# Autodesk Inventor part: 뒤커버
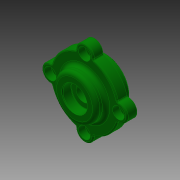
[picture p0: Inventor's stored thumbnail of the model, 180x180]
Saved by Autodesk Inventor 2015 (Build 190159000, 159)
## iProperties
Created: 2016-05
Part Number: 뒤커버
Document SubType Name: Modeling
Designer: mduedu
Density: 2.71 g/cm^3
Material: 알루미늄 6061
Appearance: 진녹색
Author: mduedu
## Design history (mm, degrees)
sketch "스케치1"
  geometry: C1 r 20 at (0, 0); C2 r 27.5 at (0, 0); 1 further point
  constraints: 2 centre point, 2 coincident
  dimensions: "d33" = 55 diameter of C2; "d34" = 40 diameter of C1
extrude "돌출1" new body sketch "스케치1" distance "d0" = 8; taper "d1" = 0 deg
extrude "돌출2" join sketch "스케치1" distance "d2" = 8; taper "d3" = 0 deg; dims "d35" = 9, "d36" = 0
sketch "스케치6"
  geometry: C1 r 17.5 at (0, 0); 2 further points
  constraints: 2 coincident, 1 centre point
  dimensions: "d42" = 35 diameter of C1
extrude "돌출4" join sketch "스케치6" distance "d43" = 8; taper "d44" = 0 deg
sketch "스케치4"
  geometry: L1 (0, -9)-(0, 16); L2 (-15, -9)-(-15, 0); L3 (-15, 0)-(-10, 0); L4 (-10, 0)-(-10, 3); L5 (-10, 3)-(-6, 3); L6 (-6, 3)-(-6, 8.7); L7 (-6, 8.7)-(-10, 8.7); L8 (-10, 8.7)-(-10, 16); L9 (20, -9)-(-20, -9) reference; L10 (17.5, 16)-(-17.5, 16) reference; 1 further point
  constraints: 16 end point, 6 parallel, 3 point on line, 2 midpoint, 2 perpendicular, 1 vertical
  dimensions: "d15" = 30 diameter of L2 L1; "d16" = 20 diameter of L8 L1; "d18" = 9 distance of L2.start L2.end; "d19" = 3 distance of L3.end L4.end; "d20" = 20 diameter of L4 L1; "d21" = 12 diameter of L6 L1; "d45" = 7.3 distance of L7.end L8.end
revolve "회전1" sketch "스케치4" stored, may be unused: angle "d22" = 90 deg
fillet "모깎기2" dims "d23" = 3
fillet "모깎기3" dims "d24" = 0.3
chamfer "모따기2" distance "d46" = 1; stored, may be unused: second distance "d47" = 2, angle "d48" = 45 deg
sketch "스케치7"
  geometry: C1 r 7 at (0, 27.5); 2 further points
  constraints: 3 vertical alignment, 1 centre point, 2 other
  dimensions: "d54" = 14 diameter of C1
extrude "돌출5" join sketch "스케치7" stored distance "d55" = 10; taper "d56" = 0 deg
fillet "모깎기6" dims "d57" = 1
sketch "스케치10"
  geometry: C1 r 17.5 at (0, 0) reference; A1 r 27.5 centre (0, 0) between (26.395, 7.718) and (7.718, 26.395) reference; A2 r 1 centre (7.999, 27.355) between (6.999, 27.373) and (7.718, 26.395) reference; A3 r 7 centre (0, 27.5) between (6.999, 27.373) and (-6.999, 27.373) reference; A4 r 1 centre (-7.999, 27.355) between (-7.718, 26.395) and (-6.999, 27.373) reference; A5 r 27.5 centre (0, 0) between (-7.718, 26.395) and (-26.395, 7.718) reference; A6 r 1 centre (-27.355, 7.999) between (-27.373, 6.999) and (-26.395, 7.718) reference; A7 r 7 centre (-27.5, 0) between (-27.373, 6.999) and (-27.373, -6.999) reference; A8 r 1 centre (-27.355, -7.999) between (-26.395, -7.718) and (-27.373, -6.999) reference; A9 r 27.5 centre (0, 0) between (-26.395, -7.718) and (-7.718, -26.395) reference; A10 r 1 centre (-7.999, -27.355) between (-6.999, -27.373) and (-7.718, -26.395) reference; A11 r 7 centre (0, -27.5) between (-6.999, -27.373) and (6.999, -27.373) reference; A12 r 1 centre (7.999, -27.355) between (7.718, -26.395) and (6.999, -27.373) reference; A13 r 27.5 centre (0, 0) between (7.718, -26.395) and (26.395, -7.718) reference; A14 r 1 centre (27.355, -7.999) between (27.373, -6.999) and (26.395, -7.718) reference; A15 r 7 centre (27.5, 0) between (27.373, -6.999) and (27.373, 6.999) reference; A16 r 1 centre (27.355, 7.999) between (26.395, 7.718) and (27.373, 6.999) reference; 4 further points
  constraints: 3 coincident
hole "구멍3" sketch "스케치10" at (0, 27.5), (-27.5, 0), (0, -27.5), (27.5, 0) diameter "d81" = 5.5; stored, may be unused: countersink angle "d85" = 90 deg, drill point angle "d87" = 118 deg; dims "d82" = 6, "d83" = 9.5, "d84" = 5.4, "d86" = 8
fillet "모깎기7" dims "d61" = 1
fillet "모깎기8" dims "d88" = 3
chamfer "모따기3" distance "d76" = 0.7; stored, may be unused: second distance "d77" = 2, angle "d78" = 30 deg
node "솔리드1"
pattern_circular "원형 패턴1" dims angle "d59" = 360 deg
node "투영된 루프1"
